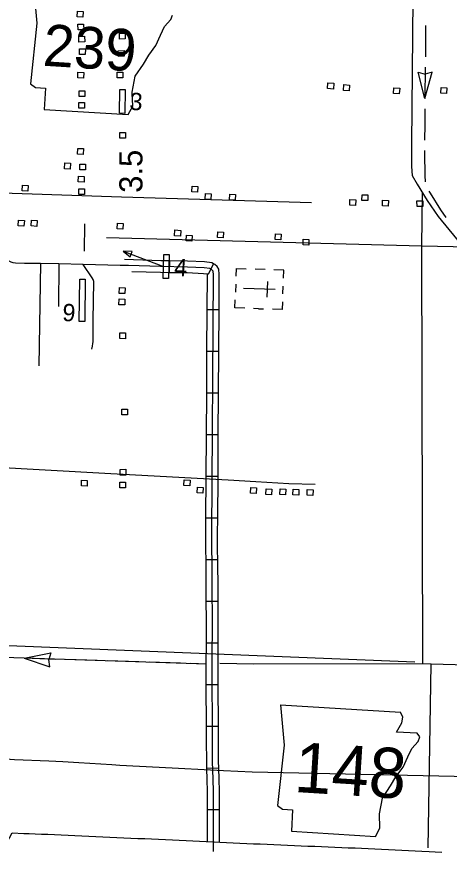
# Model space of a CAD drawing. Extents: x 1366406 to 1373462, y 376856 to 381998.
# Drawn here: x 1369269.8 to 1369358.5, y 379560.9 to 379732.3 of the extents above; entities that cross this region are included whole.
import ezdxf

# ---------------------------------------------------------------- set-up
doc = ezdxf.new("R2010")
doc.units = 0
for name, color, linetype in [('10', 7, 'Continuous'), ('21', 7, 'Continuous'), ('32', 7, 'Continuous'), ('4', 7, 'Continuous'), ('43', 7, 'Continuous'), ('45', 7, 'Continuous'), ('48', 7, 'Continuous'), ('5', 7, 'Continuous'), ('56', 7, 'Continuous'), ('57', 7, 'Continuous')]:
    doc.layers.add(name, color=color, linetype=linetype)

msp = doc.modelspace()

# ---------------------------------------------------------------- linework, layer by layer
at = {"layer": '10'}
for points in [[(1369266.74, 379560.9), (1369268.87, 379564.84), (1369271.27, 379564.76), (1369272.38, 379564.72), (1369273.58, 379564.68)], [(1369273.58, 379564.68), (1369274.85, 379564.63), (1369276.18, 379564.58), (1369277.53, 379564.52), (1369278.92, 379564.45), (1369280.32, 379564.38), (1369281.74, 379564.31), (1369283.17, 379564.25), (1369284.6, 379564.18), (1369286.03, 379564.11), (1369287.46, 379564.05), (1369288.9, 379563.99), (1369290.32, 379563.92), (1369291.75, 379563.86), (1369293.18, 379563.8), (1369294.61, 379563.74), (1369296.04, 379563.68), (1369297.46, 379563.61), (1369298.88, 379563.55), (1369300.3, 379563.49), (1369301.72, 379563.42), (1369303.13, 379563.35), (1369304.52, 379563.28), (1369305.91, 379563.21), (1369307.29, 379563.15), (1369308.65, 379563.09), (1369310.26, 379563.04), (1369311.48, 379562.94), (1369312.82, 379562.87), (1369314.2, 379562.81), (1369315.58, 379562.74), (1369316.97, 379562.68), (1369318.35, 379562.63), (1369319.75, 379562.58), (1369321.15, 379562.53), (1369322.56, 379562.47), (1369323.96, 379562.41), (1369325.36, 379562.35), (1369326.76, 379562.29), (1369328.15, 379562.22), (1369329.53, 379562.16), (1369330.91, 379562.11), (1369332.3, 379562.06), (1369333.69, 379562), (1369335.07, 379561.94), (1369336.45, 379561.88), (1369337.81, 379561.81), (1369339.18, 379561.76), (1369340.54, 379561.7), (1369341.9, 379561.64), (1369343.27, 379561.59), (1369344.64, 379561.54), (1369346.02, 379561.47), (1369347.39, 379561.41), (1369348.75, 379561.34), (1369350.12, 379561.27), (1369351.49, 379561.2), (1369352.87, 379561.12), (1369354.4, 379561.03), (1369355.61, 379560.96), (1369356.98, 379560.87)]]:
    msp.add_lwpolyline(points, dxfattribs=at)
at = {"layer": '21'}
for p, q in [((1369273.21, 379739.27), (1369273.92, 379730.99)), ((1369300.11, 379730.31), (1369301.43, 379731.74)), ((1369301.43, 379731.74), (1369301.77, 379732.68)), ((1369273.92, 379730.99), (1369272.6, 379718.58)), ((1369299.31, 379728.57), (1369300.11, 379730.31)), ((1369298.35, 379726.44), (1369299.31, 379728.57)), ((1369296.86, 379724.47), (1369298.35, 379726.44)), ((1369295.78, 379722.62), (1369296.86, 379724.47)), ((1369294.11, 379720.11), (1369295.78, 379722.62)), ((1369293.5, 379716.86), (1369294.11, 379720.11)), ((1369272.6, 379718.58), (1369273.65, 379717.83)), ((1369273.65, 379717.83), (1369275.7, 379717.7)), ((1369275.7, 379717.7), (1369275.43, 379713.32)), ((1369293.59, 379713.97), (1369293.5, 379716.86)), ((1369275.43, 379713.32), (1369292.66, 379712.24)), ((1369292.66, 379712.24), (1369293.59, 379713.97)), ((1369323.9, 379591.16), (1369324.62, 379582.88)), ((1369349.01, 379588.63), (1369348.5, 379589.61)), ((1369348.79, 379587.41), (1369349.01, 379588.63)), ((1369347.72, 379585.55), (1369348.79, 379587.41)), ((1369351.96, 379585.29), (1369347.72, 379585.55)), ((1369352.46, 379584.57), (1369351.96, 379585.29)), ((1369352.13, 379583.63), (1369352.46, 379584.57)), ((1369324.62, 379582.88), (1369323.29, 379570.47)), ((1369350.8, 379582.2), (1369352.13, 379583.63)), ((1369350.01, 379580.47), (1369350.8, 379582.2)), ((1369349.05, 379578.33), (1369350.01, 379580.47)), ((1369347.55, 379576.36), (1369349.05, 379578.33)), ((1369346.47, 379574.51), (1369347.55, 379576.36)), ((1369344.81, 379572), (1369346.47, 379574.51)), ((1369323.29, 379570.47), (1369324.34, 379569.72)), ((1369344.19, 379568.75), (1369344.81, 379572)), ((1369324.34, 379569.72), (1369326.39, 379569.59)), ((1369326.39, 379569.59), (1369326.12, 379565.21)), ((1369344.28, 379565.86), (1369344.19, 379568.75)), ((1369343.35, 379564.13), (1369344.28, 379565.86)), ((1369326.12, 379565.21), (1369343.35, 379564.13))]:
    msp.add_line(p, q, dxfattribs=at)
msp.add_lwpolyline([(1369323.9, 379591.16), (1369348.5, 379589.61)], dxfattribs=at)
at = {"layer": '32'}
for p, q in [((1369301.11, 379682.24), (1369301.08, 379679.81)), ((1369310.18, 379681.64), (1369309.04, 379679.49)), ((1369311.31, 379672.2), (1369308.88, 379672.22)), ((1369311.25, 379663.65), (1369308.82, 379663.67)), ((1369311.19, 379655.1), (1369308.76, 379655.11)), ((1369311.14, 379646.54), (1369308.71, 379646.56)), ((1369311.08, 379637.99), (1369308.65, 379638.01)), ((1369311.02, 379629.44), (1369308.59, 379629.45)), ((1369311.06, 379620.92), (1369308.63, 379620.86)), ((1369311.1, 379612.35), (1369308.67, 379612.33)), ((1369311.12, 379603.78), (1369308.69, 379603.79)), ((1369311.11, 379595.24), (1369308.68, 379595.23)), ((1369311.15, 379586.68), (1369308.72, 379586.67)), ((1369311.24, 379578.17), (1369308.81, 379578.09)), ((1369311.36, 379569.58), (1369308.93, 379569.57))]:
    msp.add_line(p, q, dxfattribs=at)
for points in [[(1369292.71, 379681.25), (1369291, 379681.3), (1369283.42, 379681.5), (1369278.43, 379681.63), (1369274.67, 379681.68), (1369271.36, 379681.71), (1369269.55, 379681.75), (1369269.04, 379681.83), (1369268.69, 379681.94), (1369268.24, 379682.16), (1369267.65, 379682.5), (1369267.11, 379682.89)], [(1369301.11, 379682.24), (1369299.33, 379682.26), (1369291.91, 379682.49)], [(1369310.18, 379681.64), (1369309.79, 379681.84), (1369308.32, 379682.03), (1369304.84, 379682.18), (1369301.11, 379682.24)], [(1369274.67, 379681.68), (1369274.33, 379660.7)], [(1369278.43, 379681.63), (1369278.37, 379672.89)], [(1369309.79, 379626.3), (1369310.14, 379679.4), (1369310.06, 379680.1), (1369309.94, 379680.29), (1369309.71, 379680.51), (1369309.42, 379680.67), (1369308.22, 379680.81), (1369304.8, 379680.97), (1369299.31, 379681.05), (1369292.71, 379681.25)], [(1369311.31, 379672.2), (1369311.35, 379679.46), (1369311.24, 379680.52), (1369310.88, 379681.07), (1369310.43, 379681.51), (1369310.18, 379681.64)], [(1369301.08, 379679.81), (1369299.28, 379679.83), (1369293.43, 379680.01)], [(1369309.05, 379679.49), (1369308.12, 379679.6), (1369304.76, 379679.75), (1369301.08, 379679.81)], [(1369308.88, 379672.22), (1369308.92, 379679.34), (1369308.9, 379679.57), (1369309.04, 379679.49)], [(1369308.82, 379663.67), (1369308.88, 379672.22)], [(1369311.25, 379663.65), (1369311.31, 379672.2)], [(1369308.76, 379655.11), (1369308.82, 379663.67)], [(1369311.19, 379655.1), (1369311.25, 379663.65)], [(1369308.71, 379646.56), (1369308.76, 379655.11)], [(1369311.14, 379646.54), (1369311.19, 379655.1)], [(1369308.65, 379638.01), (1369308.71, 379646.56)], [(1369311.08, 379637.99), (1369311.14, 379646.54)], [(1369308.59, 379629.45), (1369308.65, 379638.01)], [(1369311.02, 379629.44), (1369311.08, 379637.99)], [(1369308.63, 379620.86), (1369308.57, 379622.92), (1369308.57, 379626.31), (1369308.59, 379629.45)], [(1369311.06, 379620.92), (1369311, 379622.95), (1369311, 379626.3), (1369311.02, 379629.44)], [(1369310.15, 379561.02), (1369310.15, 379565.89), (1369310.15, 379573.38), (1369310.1, 379575.85), (1369309.98, 379579.53), (1369309.94, 379583.76), (1369309.88, 379599.59), (1369309.92, 379608.71), (1369309.87, 379614.86), (1369309.85, 379620.65), (1369309.79, 379622.93), (1369309.79, 379626.3)], [(1369308.67, 379612.33), (1369308.65, 379614.86), (1369308.63, 379620.63), (1369308.63, 379620.86)], [(1369311.1, 379612.35), (1369311.08, 379614.87), (1369311.06, 379620.67), (1369311.06, 379620.92)], [(1369308.69, 379603.79), (1369308.7, 379608.71), (1369308.67, 379612.33)], [(1369311.12, 379603.78), (1369311.13, 379608.72), (1369311.1, 379612.35)], [(1369351.48, 379599.86), (1369266.31, 379603.28), (1369179.03, 379605.1), (1369174.99, 379605.38), (1369164.74, 379605.83), (1369157.81, 379606.32), (1369154.03, 379606.43), (1369137.36, 379607.36), (1369114.78, 379608.63), (1369109.7, 379608.87), (1369095.64, 379609.67), (1369092.11, 379609.86), (1369088.17, 379609.98), (1369077.63, 379609.96), (1369054.33, 379610.2), (1369050.57, 379610.31), (1369050.29, 379610.24), (1369050.13, 379610.03), (1369050.06, 379609.75), (1369048.84, 379528.17), (1369048.72, 379524.5)], [(1369308.68, 379595.23), (1369308.67, 379599.59), (1369308.69, 379603.79)], [(1369311.11, 379595.24), (1369311.1, 379599.59), (1369311.12, 379603.78)], [(1369308.72, 379586.67), (1369308.68, 379595.23)], [(1369311.15, 379586.68), (1369311.11, 379595.24)], [(1369308.81, 379578.09), (1369308.76, 379579.5), (1369308.73, 379583.75), (1369308.72, 379586.67)], [(1369311.24, 379578.17), (1369311.19, 379579.55), (1369311.16, 379583.76), (1369311.15, 379586.68)], [(1369308.93, 379569.57), (1369308.93, 379573.37), (1369308.88, 379575.82), (1369308.81, 379578.09)], [(1369311.36, 379569.58), (1369311.36, 379573.39), (1369311.31, 379575.88), (1369311.24, 379578.17)], [(1369308.94, 379563.08), (1369308.94, 379565.89), (1369308.93, 379569.57)], [(1369311.37, 379562.94), (1369311.37, 379565.89), (1369311.36, 379569.58)]]:
    msp.add_lwpolyline(points, dxfattribs=at)
at = {"layer": '4'}
msp.add_lwpolyline([(1369435.47, 379597.25), (1369354.8, 379599.47), (1369353.11, 379599.52), (1369318.41, 379599.46), (1369311.47, 379599.63)], dxfattribs=at)
at = {"layer": '43'}
for p, q in [((1369353.53, 379715.57), (1369352.15, 379720.96)), ((1369352.15, 379720.96), (1369353.57, 379720.56)), ((1369353.53, 379715.57), (1369355.02, 379720.93)), ((1369355.02, 379720.93), (1369353.59, 379720.56)), ((1369271.33, 379600.73), (1369276.78, 379601.83)), ((1369276.78, 379601.83), (1369276.36, 379600.42)), ((1369271.33, 379600.73), (1369276.6, 379598.96)), ((1369276.6, 379598.96), (1369276.36, 379600.42))]:
    msp.add_line(p, q, dxfattribs=at)
for points in [[(1369351.3, 379765.85), (1369350.74, 379706.18), (1369350.79, 379701.61), (1369350.9, 379699.72), (1369351.92, 379697.97), (1369354.01, 379694.59), (1369356.25, 379691.35), (1369360.01, 379686.74), (1369372.72, 379671.36), (1369378.58, 379664.26), (1369387.39, 379653.76), (1369391.13, 379649.16), (1369393.17, 379646.84), (1369396.82, 379639.03), (1369400.35, 379631.05), (1369400.91, 379629.73), (1369401.34, 379628.9), (1369401.71, 379628.31), (1369402.26, 379627.78), (1369403.15, 379627.32), (1369405.31, 379626.33)], [(1369353.67, 379730.54), (1369353.61, 379724.13)], [(1369353.59, 379721.99), (1369353.53, 379715.57)], [(1369353.51, 379713.43), (1369353.49, 379710.23)], [(1369353.49, 379710.23), (1369353.46, 379707.02)], [(1369353.44, 379704.88), (1369353.43, 379704.31), (1369353.47, 379699.75), (1369353.55, 379698.47)], [(1369330.23, 379694.11), (1369291.29, 379695.28), (1369260.68, 379696.32), (1369256.86, 379696.38), (1369256.17, 379696.43), (1369246.89, 379696.73), (1369242.78, 379696.83), (1369229.88, 379697.28), (1369215.77, 379697.69), (1369182.62, 379698.72), (1369149.51, 379699.65), (1369141.99, 379699.82)], [(1369354.35, 379696.54), (1369354.61, 379696.1), (1369356.7, 379692.72), (1369357.8, 379691.13)], [(1369330.99, 379636.35), (1369325.61, 379636.45), (1369318.87, 379636.87), (1369313.14, 379637.23), (1369289.1, 379638.56), (1369263.36, 379640), (1369259.23, 379640.24), (1369251.56, 379640.3), (1369245.01, 379640.33), (1369235.57, 379640.46), (1369229.12, 379640.49), (1369219.48, 379640.74), (1369171.97, 379640.78), (1369140.72, 379640.51), (1369135.54, 379640.55), (1369128.21, 379640.55), (1369116.9, 379640.57), (1369111.29, 379640.68), (1369105.6, 379640.72), (1369057.11, 379640.87), (1369052.46, 379641), (1369046.89, 379640.99)], [(1369308.74, 379599.51), (1369267.17, 379600.87), (1369263.14, 379601.12), (1369256.36, 379601.23), (1369248, 379601.32)], [(1369277.74, 379600.42), (1369271.33, 379600.73)], [(1369286.3, 379600.24), (1369279.88, 379600.45)], [(1369294.84, 379599.97), (1369288.43, 379600.17)], [(1369303.39, 379599.69), (1369296.98, 379599.9)], [(1369308.74, 379599.51), (1369305.53, 379599.62)], [(1369362.71, 379576.35), (1369318.1, 379577.32), (1369312.19, 379577.6), (1369299.01, 379578.27), (1369290.93, 379578.7), (1369289.32, 379578.85), (1369282.52, 379579.24), (1369279.24, 379579.47), (1369276.39, 379579.59), (1369269.37, 379579.87), (1369264.83, 379580.18), (1369258.37, 379580.44), (1369197.74, 379581.18), (1369166.71, 379581.62), (1369153.03, 379581.7), (1369141.95, 379581.92)]]:
    msp.add_lwpolyline(points, dxfattribs=at)
at = {"layer": '45'}
msp.add_lwpolyline([(1369285.19, 379664.11), (1369285.35, 379664.76), (1369285.44, 379665.26), (1369285.5, 379665.65), (1369285.5, 379670.03), (1369285.59, 379678.01), (1369285.46, 379678.44), (1369285.27, 379678.75), (1369283.42, 379681.5)], dxfattribs=at)
at = {"layer": '5'}
for points in [[(1369352.88, 379685.25), (1369353.03, 379696.42)], [(1369352.88, 379685.25), (1369288.18, 379686.93)], [(1369353.11, 379599.52), (1369352.88, 379685.25)], [(1369436.83, 379683.49), (1369352.88, 379685.25)], [(1369354.2, 379561.8), (1369354.8, 379599.47)]]:
    msp.add_lwpolyline(points, dxfattribs=at)
at = {"layer": '56'}
for points in [[(1369282.18, 379732.29), (1369282.24, 379733.46), (1369283.41, 379733.4), (1369283.35, 379732.23)], [(1369282.4, 379729.61), (1369282.35, 379730.78), (1369283.52, 379730.82), (1369283.57, 379729.65)], [(1369282.57, 379727.13), (1369282.56, 379728.3), (1369283.73, 379728.32), (1369283.75, 379727.15)], [(1369290.89, 379727.76), (1369290.87, 379728.93), (1369292.04, 379728.95), (1369292.07, 379727.78)], [(1369282.68, 379724.6), (1369282.7, 379725.77), (1369283.87, 379725.75), (1369283.85, 379724.58)], [(1369290.68, 379724.17), (1369290.63, 379725.34), (1369291.81, 379725.38), (1369291.85, 379724.21)], [(1369282.33, 379719.78), (1369282.36, 379720.95), (1369283.53, 379720.92), (1369283.51, 379719.75)], [(1369290.4, 379719.79), (1369290.39, 379720.96), (1369291.56, 379720.97), (1369291.58, 379719.8)], [(1369333.57, 379717.57), (1369333.64, 379718.74), (1369334.81, 379718.67), (1369334.74, 379717.5)], [(1369336.84, 379717.22), (1369336.91, 379718.39), (1369338.08, 379718.32), (1369338.01, 379717.15)], [(1369282.6, 379715.95), (1369282.62, 379717.12), (1369283.79, 379717.11), (1369283.78, 379715.94)], [(1369290.95, 379717.43), (1369292.07, 379717.41), (1369292, 379712.49), (1369290.87, 379712.51)], [(1369347.09, 379716.57), (1369347.17, 379717.74), (1369348.34, 379717.67), (1369348.26, 379716.5)], [(1369356.76, 379716.66), (1369356.83, 379717.83), (1369358.01, 379717.75), (1369357.93, 379716.58)], [(1369282.53, 379713.56), (1369282.54, 379714.73), (1369283.71, 379714.72), (1369283.7, 379713.55)], [(1369290.96, 379707.4), (1369290.93, 379708.57), (1369292.1, 379708.6), (1369292.13, 379707.43)], [(1369282.27, 379704.14), (1369282.31, 379705.31), (1369283.49, 379705.26), (1369283.44, 379704.09)], [(1369279.57, 379701.15), (1369279.65, 379702.32), (1369280.82, 379702.25), (1369280.75, 379701.08)], [(1369282.71, 379700.93), (1369282.73, 379702.1), (1369283.9, 379702.08), (1369283.88, 379700.91)], [(1369282.43, 379698.42), (1369282.47, 379699.59), (1369283.64, 379699.55), (1369283.6, 379698.38)], [(1369270.89, 379696.62), (1369270.96, 379697.79), (1369272.14, 379697.72), (1369272.06, 379696.55)], [(1369305.73, 379696.38), (1369305.8, 379697.54), (1369306.97, 379697.47), (1369306.9, 379696.3)], [(1369282.52, 379695.86), (1369282.54, 379697.04), (1369283.71, 379697.02), (1369283.69, 379695.84)], [(1369308.42, 379694.9), (1369308.49, 379696.07), (1369309.66, 379696), (1369309.59, 379694.83)], [(1369313.41, 379694.73), (1369313.48, 379695.9), (1369314.65, 379695.83), (1369314.58, 379694.66)], [(1369340.61, 379694.61), (1369340.62, 379695.78), (1369341.8, 379695.77), (1369341.79, 379694.6)], [(1369338.11, 379693.65), (1369338.14, 379694.82), (1369339.32, 379694.79), (1369339.28, 379693.62)], [(1369344.82, 379693.51), (1369344.85, 379694.68), (1369346.02, 379694.65), (1369345.99, 379693.48)], [(1369351.92, 379693.37), (1369351.89, 379694.54), (1369353.07, 379694.57), (1369353.1, 379693.4)], [(1369270.12, 379689.43), (1369270.19, 379690.6), (1369271.36, 379690.53), (1369271.29, 379689.36)], [(1369272.74, 379689.39), (1369272.82, 379690.56), (1369273.99, 379690.49), (1369273.92, 379689.32)], [(1369290.37, 379688.8), (1369290.44, 379689.97), (1369291.61, 379689.89), (1369291.54, 379688.73)], [(1369302.19, 379687.4), (1369302.26, 379688.57), (1369303.44, 379688.49), (1369303.36, 379687.32)], [(1369304.56, 379686.35), (1369304.64, 379687.52), (1369305.81, 379687.45), (1369305.74, 379686.28)], [(1369310.98, 379687.01), (1369311.05, 379688.18), (1369312.23, 379688.11), (1369312.15, 379686.94)], [(1369322.78, 379686.62), (1369322.85, 379687.78), (1369324.02, 379687.71), (1369323.95, 379686.54)], [(1369328.52, 379685.51), (1369328.56, 379686.68), (1369329.73, 379686.64), (1369329.7, 379685.47)], [(1369293.06, 379683.09), (1369293.47, 379684.16), (1369291.66, 379684.24)], [(1369299.96, 379683.54), (1369301.08, 379683.51), (1369300.96, 379678.59), (1369299.84, 379678.62)], [(1369282.74, 379678.49), (1369283.86, 379678.46), (1369283.74, 379669.8), (1369282.61, 379669.82)], [(1369290.82, 379675.57), (1369290.85, 379676.74), (1369292.03, 379676.71), (1369291.99, 379675.54)], [(1369290.77, 379673.24), (1369290.79, 379674.41), (1369291.97, 379674.39), (1369291.95, 379673.22)], [(1369290.95, 379666.29), (1369290.96, 379667.46), (1369292.13, 379667.44), (1369292.12, 379666.27)], [(1369291.35, 379650.65), (1369291.37, 379651.82), (1369292.54, 379651.8), (1369292.52, 379650.63)], [(1369291.01, 379638.28), (1369290.99, 379639.45), (1369292.17, 379639.46), (1369292.18, 379638.29)], [(1369304.1, 379636.14), (1369304.17, 379637.31), (1369305.35, 379637.23), (1369305.27, 379636.07)], [(1369283.05, 379636.04), (1369283.07, 379637.21), (1369284.25, 379637.19), (1369284.23, 379636.01)], [(1369290.94, 379635.68), (1369290.94, 379636.85), (1369292.12, 379636.84), (1369292.12, 379635.67)], [(1369306.79, 379634.67), (1369306.87, 379635.83), (1369308.04, 379635.76), (1369307.97, 379634.59)], [(1369317.76, 379634.55), (1369317.83, 379635.72), (1369319, 379635.65), (1369318.93, 379634.48)], [(1369320.86, 379634.3), (1369320.93, 379635.47), (1369322.11, 379635.4), (1369322.03, 379634.23)], [(1369323.74, 379634.28), (1369323.8, 379635.45), (1369324.97, 379635.39), (1369324.91, 379634.22)], [(1369326.46, 379634.21), (1369326.51, 379635.38), (1369327.69, 379635.33), (1369327.64, 379634.16)], [(1369329.34, 379634.15), (1369329.39, 379635.32), (1369330.57, 379635.27), (1369330.51, 379634.1)]]:
    msp.add_lwpolyline(points, close=True, dxfattribs=at)
for points in [[(1369283.67, 379689.86), (1369283.62, 379684.2)], [(1369291.66, 379684.24), (1369299.9, 379681.08)]]:
    msp.add_lwpolyline(points, dxfattribs=at)
at = {"layer": '57'}
for p, q in [((1369320.72, 379680.47), (1369318.7, 379680.55)), ((1369314.74, 379677.46), (1369314.68, 379675.84)), ((1369321.25, 379678.02), (1369321.12, 379674.77)), ((1369324.39, 379675.45), (1369324.45, 379677.07)), ((1369322.8, 379676.34), (1369316.33, 379676.59)), ((1369319.56, 379676.46), (1369319.56, 379676.46)), ((1369319.56, 379676.46), (1369319.56, 379676.46)), ((1369319.4, 379672.42), (1369318.38, 379672.46)), ((1369319.4, 379672.42), (1369320.4, 379672.38))]:
    msp.add_line(p, q, dxfattribs=at)
for points in [[(1369314.8, 379679.08), (1369314.87, 379680.7), (1369316.89, 379680.62)], [(1369324.52, 379678.7), (1369324.58, 379680.32), (1369322.56, 379680.4)], [(1369316.57, 379672.53), (1369314.55, 379672.61), (1369314.61, 379674.23)], [(1369324.32, 379673.84), (1369324.26, 379672.23), (1369322.24, 379672.31)]]:
    msp.add_lwpolyline(points, dxfattribs=at)

# ---------------------------------------------------------------- texts
at = {"layer": '21'}
for s, height, p in [('239', 8.554, (1369275.02, 379722.29)), ('148', 10.264, (1369326.53, 379573.27))]:
    msp.add_text(s, height=height, rotation=356.4139, dxfattribs=at).set_placement(p)
at = {"layer": '48'}
msp.add_text('3.5', height=4.752, rotation=90.014, dxfattribs=at).set_placement((1369295.59, 379696.2))
at = {"layer": '56'}
for s, p in [('3', (1369292.86, 379713.24)), ('4', (1369302.02, 379679.2)), ('9', (1369279.08, 379669.92))]:
    msp.add_text(s, height=3.56, rotation=356.4139, dxfattribs=at).set_placement(p)

doc.saveas('drawing.dxf')
